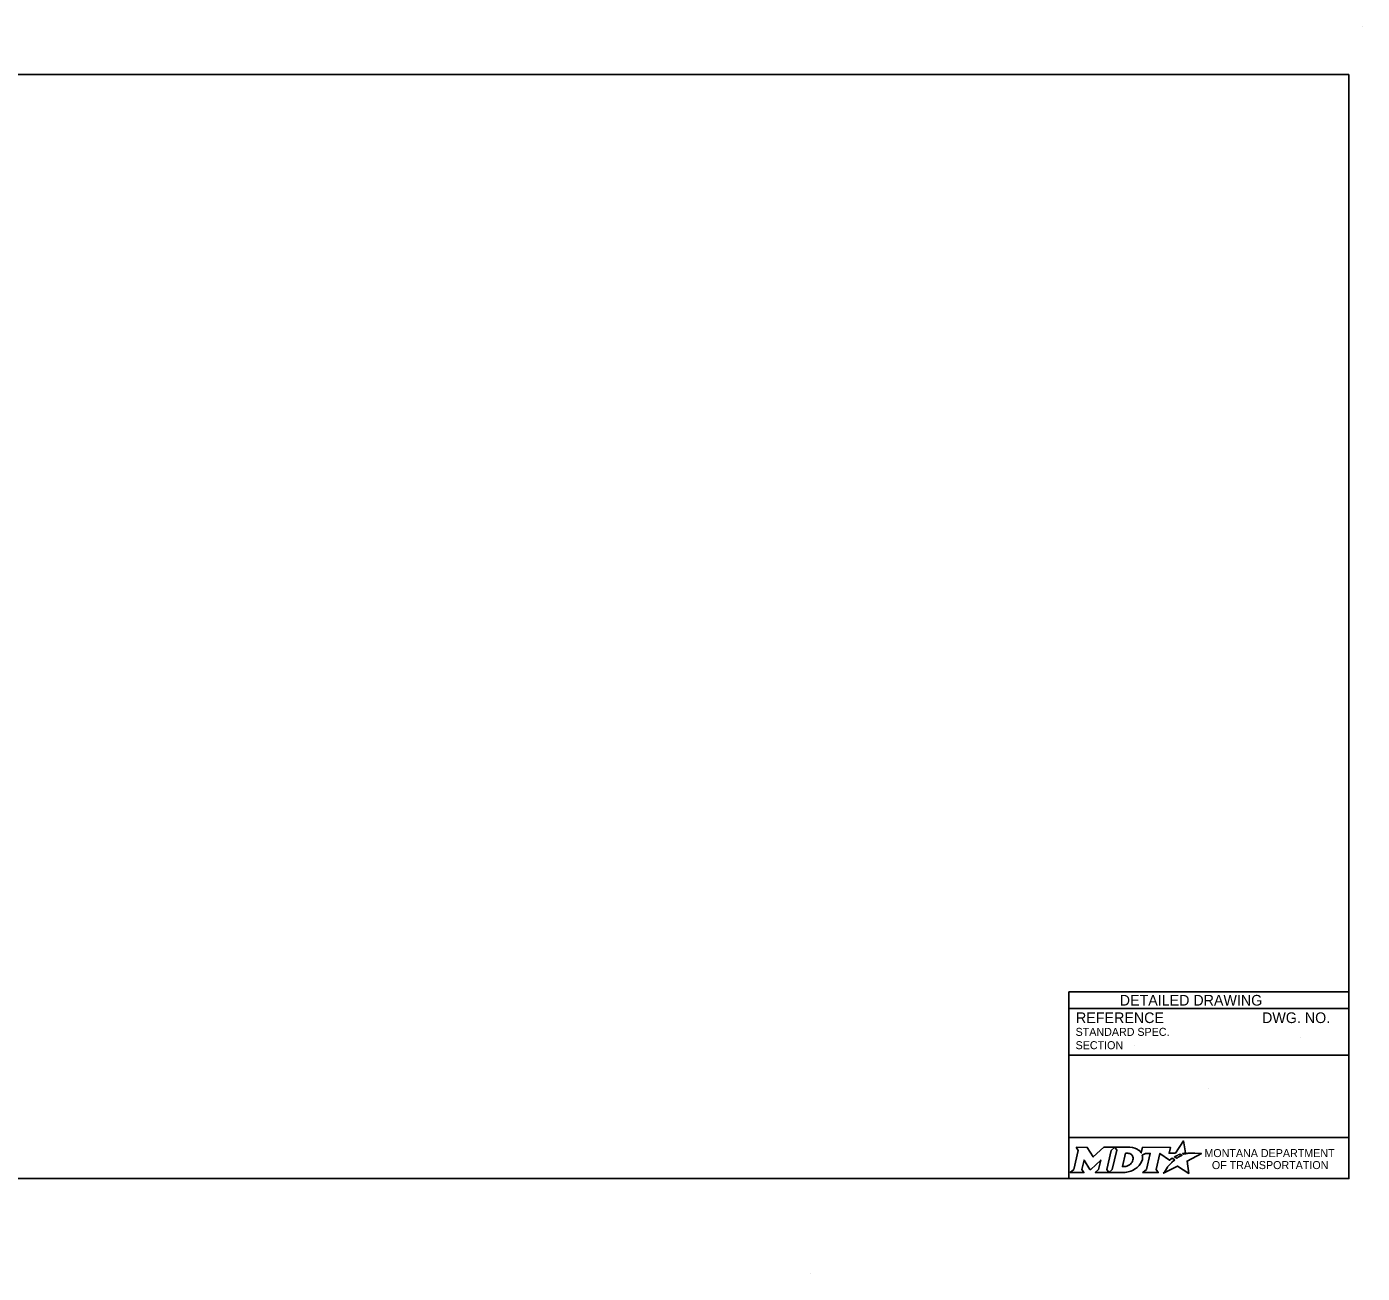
# Model space of a CAD drawing. Extents: x 49991.4 to 50021, y 49987.6 to 50011.4.
# Drawn here: x 50011.02 to 50021.04, y 49999.18 to 50008.52 of the extents above; entities that cross this region are included whole.
import ezdxf

# ---------------------------------------------------------------- set-up
doc = ezdxf.new("R2010")
doc.units = 0
for name, color, linetype in [('Default', 7, 'Continuous'), ('Level 1', 7, 'Continuous'), ('Level 4', 7, 'Continuous')]:
    doc.layers.add(name, color=color, linetype=linetype)

msp = doc.modelspace()

# ---------------------------------------------------------------- linework, layer by layer
at = {"layer": 'Default'}
for points in [[(50018.893, 50000.121), (50018.907, 50000.097), (50018.874, 49999.954), (50018.848, 49999.931), (50018.95, 49999.931), (50018.936, 49999.954), (50018.952, 50000.024), (50018.996, 49999.955), (50019.002, 49999.955), (50019.077, 50000.025), (50019.06, 49999.954), (50019.035, 49999.932), (50019.137, 49999.932), (50019.123, 49999.955), (50019.156, 50000.097)], [(50019.156, 50000.097), (50019.182, 50000.121), (50019.099, 50000.121), (50019.02, 50000.048), (50018.975, 50000.12), (50018.893, 50000.121)], [(50019.295, 50000.121), (50019.182, 50000.121), (50019.196, 50000.098), (50019.163, 49999.954), (50019.137, 49999.932), (50019.248, 49999.932)], [(50019.7, 50000.068), (50019.69, 50000.074), (50019.702, 50000.076), (50019.713, 50000.078), (50019.696, 50000.168), (50019.636, 50000.077), (50019.589, 50000.076), (50019.599, 50000.12), (50019.39, 50000.121), (50019.38, 50000.078), (50019.374, 50000.086)], [(50019.319, 50000.034), (50019.318, 50000.026), (50019.315, 50000.017), (50019.311, 50000.008), (50019.305, 50000.001), (50019.299, 49999.994), (50019.291, 49999.988), (50019.282, 49999.983), (50019.273, 49999.979), (50019.264, 49999.977), (50019.255, 49999.976), (50019.239, 49999.976), (50019.263, 50000.076), (50019.279, 50000.076), (50019.286, 50000.075), (50019.294, 50000.073), (50019.301, 50000.07), (50019.307, 50000.066), (50019.311, 50000.061), (50019.315, 50000.055), (50019.318, 50000.049), (50019.319, 50000.042), (50019.32, 50000.038), (50019.319, 50000.034)], [(50019.387, 50000.062), (50019.411, 50000.075), (50019.448, 50000.075), (50019.42, 49999.954), (50019.392, 49999.931), (50019.508, 49999.931), (50019.491, 49999.954), (50019.52, 50000.075), (50019.591, 50000.023), (50019.612, 50000.038), (50019.632, 50000.027)], [(50019.576, 49999.971), (50019.561, 49999.947), (50019.556, 49999.939), (50019.55, 49999.931), (50019.548, 49999.926), (50019.653, 49999.979), (50019.737, 49999.924), (50019.724, 50000.017), (50019.831, 50000.075), (50019.782, 50000.076), (50019.751, 50000.077), (50019.731, 50000.077), (50019.724, 50000.075), (50019.719, 50000.074), (50019.711, 50000.072), (50019.7, 50000.068)], [(50019.59, 49999.987), (50019.59, 49999.987)], [(50019.65, 50000.04), (50019.648, 50000.039), (50019.629, 50000.048), (50019.639, 50000.054), (50019.644, 50000.056), (50019.652, 50000.06), (50019.658, 50000.063), (50019.666, 50000.066), (50019.673, 50000.068), (50019.685, 50000.061), (50019.681, 50000.059), (50019.676, 50000.056), (50019.672, 50000.054), (50019.667, 50000.051), (50019.665, 50000.05), (50019.662, 50000.049), (50019.66, 50000.047), (50019.658, 50000.046), (50019.655, 50000.044), (50019.652, 50000.042), (50019.65, 50000.04)], [(50019.293, 49999.939), (50019.302, 49999.942), (50019.315, 49999.947), (50019.335, 49999.958)]]:
    msp.add_lwpolyline(points, dxfattribs=at)
for centre, radius, start, end in [((50019.274, 50000.059), 0.118, 300.9103, 339.1383), ((50019.319, 50000.042), 0.0709, 339.5329, 15.8582)]:
    msp.add_arc(centre, radius, start, end, dxfattribs=at)
for centre, major_axis, ratio, start_param, end_param in [((50019.293, 50000.073), (0.0834, -0.0037), 0.568097, 0.61298, 1.570796), ((50019.349, 50000.081), (0.0361, -0.0295), 0.469099, 1.225588, 1.570796), ((50019.583, 49999.979), (-0.00694, -0.00806), 0.008222, 0, 3.137361), ((50019.6, 49999.997), (-0.0098, -0.0102), 0.016458, 3.141593, 6.279097), ((50019.621, 50000.017), (-0.0112, -0.0097), 0.021651, 3.157348, 6.283185), ((50019.248, 50000.08), (0, 0.148), 0.987302, 3.139398, 3.456847)]:
    msp.add_ellipse(centre, major_axis=major_axis, ratio=ratio, start_param=start_param, end_param=end_param, dxfattribs=at)
at = {"layer": 'Level 1'}
for p, q in [((50021.038, 50008.524), (50021.038, 50008.524)), ((50016.9, 49999.176), (50016.9, 49999.176))]:
    msp.add_line(p, q, dxfattribs=at)
msp.add_lwpolyline([(50020.938, 50008.165), (50009.737, 50008.165), (50009.737, 49999.886), (50020.938, 49999.886)], close=True, dxfattribs=at)
at = {"layer": 'Level 4'}
for p, q in [((50020.938, 50001.286), (50018.838, 50001.286)), ((50018.838, 50001.286), (50018.838, 49999.886)), ((50020.938, 50001.161), (50018.838, 50001.161)), ((50019.332, 50000.886), (50019.332, 50000.886)), ((50020.574, 50000.946), (50020.574, 50000.946)), ((50020.938, 50000.811), (50018.838, 50000.811)), ((50019.888, 50000.562), (50019.888, 50000.562)), ((50020.938, 50000.193), (50018.838, 50000.193))]:
    msp.add_line(p, q, dxfattribs=at)

# ---------------------------------------------------------------- texts
at = {"layer": 'Default'}
for s, p in [('MONTANA DEPARTMENT', (50019.854, 50000.047)), ('OF TRANSPORTATION', (50019.91, 49999.957))]:
    msp.add_text(s, height=0.06, dxfattribs=at).set_placement(p)
at = {"layer": 'Level 4'}
for s, height, p in [('DETAILED DRAWING', 0.0799, (50019.219, 50001.183)), ('REFERENCE', 0.08, (50018.891, 50001.052)), ('DWG. NO.', 0.08, (50020.286, 50001.052)), ('STANDARD SPEC.', 0.06, (50018.888, 50000.956)), ('SECTION', 0.06, (50018.888, 50000.856))]:
    msp.add_text(s, height=height, dxfattribs=at).set_placement(p)

doc.saveas('drawing.dxf')
